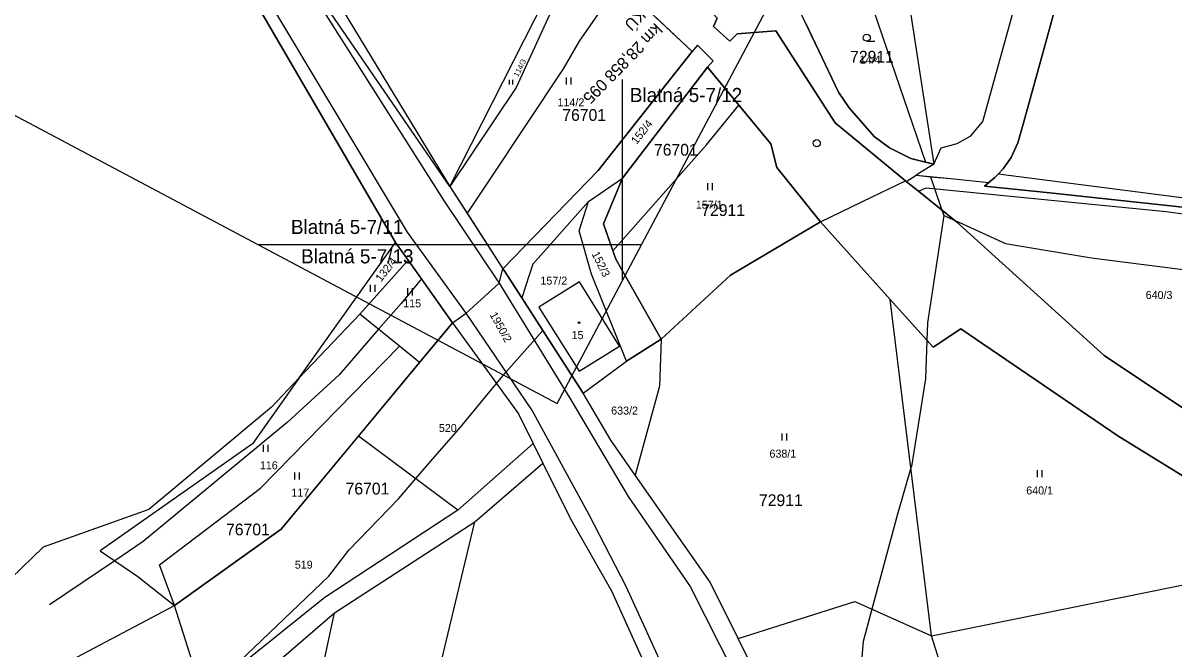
# Model space of a CAD drawing. Extents: x -794765 to -785424, y -1118958 to -1108731.
# Drawn here: x -789502.2 to -789257.8, y -1114585.8 to -1114452.9 of the extents above; entities that cross this region are included whole.
import ezdxf

# ---------------------------------------------------------------- set-up
doc = ezdxf.new("R2010")
doc.units = 0
for name, color, linetype in [('Level 66', 7, 'Continuous'), ('Level 71', 7, 'Continuous'), ('Level 75', 7, 'Continuous'), ('Level 76', 7, 'Continuous'), ('Level 77', 7, 'Continuous'), ('Level 78', 7, 'Continuous'), ('Level 79', 7, 'Continuous'), ('Level 81', 7, 'Continuous'), ('Vrstva 1', 7, 'Continuous'), ('Vrstva 53', 7, 'Continuous')]:
    doc.layers.add(name, color=color, linetype=linetype)

msp = doc.modelspace()

# ---------------------------------------------------------------- linework, layer by layer
at = {"layer": 'Level 66'}
for p, q in [((-789323.04, -1114456.77), (-789321.29, -1114456.77)), ((-789386.81, -1114465.98), (-789386.81, -1114464.48)), ((-789385.81, -1114465.98), (-789385.81, -1114464.48)), ((-789398.9, -1114465.95), (-789398.9, -1114464.95)), ((-789398.23, -1114465.95), (-789398.23, -1114464.95)), ((-789356.8, -1114488.4), (-789356.8, -1114486.9)), ((-789355.8, -1114488.4), (-789355.8, -1114486.9)), ((-789428.43, -1114510), (-789428.43, -1114508.5)), ((-789427.43, -1114510), (-789427.43, -1114508.5)), ((-789420.51, -1114510.74), (-789420.51, -1114509.24)), ((-789419.51, -1114510.74), (-789419.51, -1114509.24)), ((-789340.98, -1114541.58), (-789340.98, -1114540.08)), ((-789339.98, -1114541.58), (-789339.98, -1114540.08)), ((-789451.14, -1114543.99), (-789451.14, -1114542.49)), ((-789450.14, -1114543.99), (-789450.14, -1114542.49)), ((-789444.52, -1114549.86), (-789444.52, -1114548.36)), ((-789443.52, -1114549.86), (-789443.52, -1114548.36)), ((-789286.76, -1114549.37), (-789286.76, -1114547.87)), ((-789285.76, -1114549.37), (-789285.76, -1114547.87))]:
    msp.add_line(p, q, dxfattribs=at)
msp.add_circle((-789323.04, -1114456.02), 0.75, dxfattribs=at)
at = {"layer": 'Level 71'}
msp.add_lwpolyline([(-790360.41, -1114017.5), (-789388.79, -1114533.68), (-789259.98, -1114291.21)], dxfattribs=at)
at = {"layer": 'Level 75'}
for p, q in [((-789360.15, -1114458.92), (-789383.79, -1114436.65)), ((-789411.55, -1114487.64), (-789387.36, -1114439.86)), ((-789315.13, -1114441.52), (-789308.78, -1114482.88)), ((-789374.9, -1114485.84), (-789356.86, -1114462.31)), ((-789308.78, -1114482.88), (-789307.22, -1114479.43)), ((-789308.78, -1114482.88), (-789312.54, -1114485.23)), ((-789382.15, -1114490.8), (-789374.9, -1114485.84)), ((-789314.65, -1114486.55), (-789314.84, -1114486.39)), ((-789314.65, -1114486.55), (-789314.84, -1114486.39)), ((-789314.65, -1114486.55), (-789312.54, -1114485.23)), ((-789312.07, -1114488.61), (-789314.65, -1114486.55)), ((-789411.55, -1114487.64), (-789400.29, -1114505.09)), ((-789297.1, -1114486.75), (-789298.04, -1114487.53)), ((-789298.04, -1114487.53), (-789284.18, -1114488.99)), ((-789332.87, -1114495.13), (-789318.04, -1114511.65)), ((-789443.55, -1114528.27), (-789423.09, -1114499.54)), ((-789423.09, -1114499.54), (-789420.43, -1114503.28)), ((-789420.43, -1114503.28), (-789430.68, -1114514.72)), ((-789420.43, -1114503.28), (-789410.99, -1114516.56)), ((-789383.25, -1114531.51), (-789396.3, -1114511.28)), ((-789309.27, -1114583.03), (-789318.04, -1114511.65)), ((-789430.68, -1114514.72), (-789443.55, -1114528.27)), ((-789422.26, -1114521.55), (-789430.68, -1114514.72)), ((-789418, -1114525), (-789410.99, -1114516.56)), ((-789366.73, -1114520.04), (-789374.05, -1114524.74)), ((-789418, -1114525), (-789422.26, -1114521.55)), ((-789430.96, -1114540.62), (-789418, -1114525)), ((-789383.25, -1114531.51), (-789374.05, -1114524.74)), ((-789409.89, -1114556.32), (-789430.96, -1114540.62)), ((-789393.88, -1114542.19), (-789409.89, -1114556.32)), ((-789393.88, -1114542.19), (-789391.8, -1114546.4)), ((-789406.25, -1114558.84), (-789391.8, -1114546.4)), ((-789436.07, -1114578.19), (-789406.25, -1114558.84)), ((-789420.11, -1114616.54), (-789406.25, -1114558.84)), ((-789309.27, -1114583.03), (-789233.08, -1114567.59)), ((-789463.99, -1114595.65), (-789470.03, -1114576.58)), ((-789298.53, -1114616.71), (-789309.27, -1114583.03))]:
    msp.add_line(p, q, dxfattribs=at)
for points in [[(-789411.55, -1114487.64), (-789444.12, -1114440.1), (-789460.39, -1114416.23), (-789471.74, -1114406.17), (-789505.63, -1114376.09), (-789563.4, -1114324.15), (-789590.47, -1114299.37)], [(-789587.26, -1114300.1), (-789562.09, -1114321.4), (-789502.74, -1114374.33), (-789470.17, -1114403.72), (-789452.65, -1114419.15), (-789441.48, -1114438.37), (-789411.55, -1114487.64)], [(-789575.6, -1114332.86), (-789515.81, -1114384.07), (-789480.88, -1114415.35), (-789466.19, -1114428.84), (-789454.55, -1114445.52), (-789423.09, -1114499.54)], [(-789295.13, -1114484.99), (-789294.08, -1114483.87), (-789292.39, -1114481.46), (-789290.93, -1114478.35), (-789289.8, -1114474.35), (-789285.34, -1114458.22), (-789279.32, -1114436.33), (-789271.12, -1114410.79), (-789270.71, -1114410.22)], [(-789307.22, -1114479.43), (-789303.82, -1114478.46), (-789300.96, -1114476.84), (-789298.42, -1114473.84), (-789291.48, -1114448.78), (-789289.96, -1114449.38), (-789290.68, -1114440.44), (-789292.59, -1114437.73), (-789295.23, -1114435.63), (-789298.36, -1114434.17), (-789296.75, -1114428.57), (-789292.67, -1114429.19), (-789288.24, -1114427.96), (-789283.63, -1114424.14), (-789281.74, -1114420.18), (-789283.43, -1114419.82)], [(-789383.79, -1114436.65), (-789386.1, -1114441.7), (-789397.47, -1114466.61), (-789411.55, -1114487.64)], [(-789308.78, -1114482.88), (-789313.67, -1114481.68), (-789318.19, -1114479.4), (-789321.47, -1114476.97), (-789326.78, -1114470.92), (-789329.07, -1114467.56), (-789338.28, -1114448.1)], [(-789314.84, -1114486.39), (-789329.78, -1114474.08), (-789342.35, -1114454.54), (-789350.58, -1114455.19), (-789352.15, -1114456.75), (-789355.6, -1114453.64), (-789354.83, -1114451.89)], [(-789360.15, -1114458.92), (-789380.05, -1114484.2), (-789400.29, -1114505.09)], [(-789356.86, -1114462.31), (-789355.65, -1114460.93), (-789359, -1114457.59), (-789360.15, -1114458.92)], [(-789356.86, -1114462.31), (-789343.4, -1114478.53), (-789342.11, -1114483.58), (-789332.87, -1114495.13)], [(-789111.22, -1114470.02), (-789114.33, -1114476.68), (-789149.84, -1114486.32), (-789208.24, -1114494.14), (-789229.78, -1114493.4), (-789295.13, -1114484.99)], [(-789284.18, -1114488.99), (-789233.65, -1114494.43), (-789208.22, -1114495.86), (-789148.09, -1114487.9), (-789114.34, -1114478.64)], [(-789366.73, -1114520.04), (-789376.32, -1114503.06), (-789378.92, -1114495.53), (-789374.9, -1114485.84)], [(-789332.87, -1114495.13), (-789321.86, -1114489.79), (-789314.84, -1114486.39)], [(-789312.54, -1114485.23), (-789305.22, -1114485.95), (-789297.1, -1114486.75)], [(-789297.1, -1114486.75), (-789295.82, -1114485.71), (-789295.13, -1114484.99)], [(-789312.07, -1114488.61), (-789310.41, -1114487.87), (-789259.48, -1114492.92), (-789235.33, -1114496.28)], [(-789234.48, -1114549.02), (-789272.62, -1114523.48), (-789303.95, -1114495.11), (-789312.07, -1114488.61)], [(-789382.15, -1114490.8), (-789393.94, -1114504.09), (-789394.71, -1114506.43), (-789396.3, -1114511.28)], [(-789374.05, -1114524.74), (-789381.49, -1114506.27), (-789384.12, -1114497), (-789382.15, -1114490.8)], [(-789366.73, -1114520.04), (-789351.99, -1114506.47), (-789332.87, -1114495.13)], [(-789410.99, -1114516.56), (-789408.1, -1114514.5), (-789401.09, -1114508.13), (-789400.29, -1114505.09)], [(-789396.3, -1114511.28), (-789397.71, -1114509.09), (-789400.07, -1114505.43), (-789400.29, -1114505.09)], [(-789384.13, -1114526.83), (-789375.58, -1114521.52), (-789384.04, -1114507.86), (-789392.66, -1114513.22), (-789392.08, -1114514.15), (-789384.13, -1114526.83)], [(-789318.04, -1114511.65), (-789308.97, -1114521.75), (-789303.08, -1114517.85), (-789269.72, -1114540.6), (-789233.09, -1114563.18)], [(-789410.99, -1114516.56), (-789396.98, -1114535.89), (-789393.88, -1114542.19)], [(-789366.73, -1114520.04), (-789367.05, -1114530.02), (-789372.22, -1114548.94)], [(-789470.03, -1114576.58), (-789473.24, -1114567.94), (-789451.79, -1114551.65), (-789422.26, -1114521.55)], [(-789443.55, -1114528.27), (-789449.47, -1114534.51), (-789475.51, -1114556.18), (-789497.95, -1114564.23), (-789509.41, -1114575.22), (-789534.19, -1114601.87), (-789554.52, -1114590.86), (-789577.64, -1114602.12), (-789597.15, -1114613.07), (-789597.74, -1114600.43)], [(-789443.55, -1114528.27), (-789453.5, -1114542.25), (-789485.82, -1114565.02), (-789477.82, -1114570.42), (-789470.03, -1114576.58)], [(-789372.22, -1114548.94), (-789377.37, -1114541.51), (-789383.25, -1114531.51)], [(-789470.03, -1114576.58), (-789447.37, -1114560.39), (-789430.96, -1114540.62)], [(-789391.8, -1114546.4), (-789385.98, -1114558.19), (-789377.23, -1114573.5), (-789352.2, -1114628.9), (-789350.65, -1114631.28)], [(-789350.34, -1114583.64), (-789356.32, -1114571.64), (-789372.22, -1114548.94)], [(-789409.89, -1114556.32), (-789438.14, -1114574.88), (-789463.99, -1114595.65)], [(-789606.95, -1114640.95), (-789582.62, -1114635.01), (-789539.25, -1114613.22), (-789470.03, -1114576.58)], [(-789350.34, -1114583.64), (-789325.57, -1114575.75), (-789309.27, -1114583.03)], [(-789494.79, -1114613.58), (-789461.11, -1114599.74), (-789436.07, -1114578.19)], [(-789473.76, -1114714.5), (-789446.6, -1114627.26), (-789436.07, -1114578.19)], [(-789326.78, -1114632.68), (-789331.75, -1114620.93), (-789350.34, -1114583.64)]]:
    msp.add_lwpolyline(points, dxfattribs=at)
at = {"layer": 'Level 77'}
for p, q in [((-789445.06, -1114439.9), (-789412.76, -1114490.76)), ((-789420.6, -1114497.33), (-789452.44, -1114444.13)), ((-789412.76, -1114490.76), (-789401.09, -1114508.13)), ((-789408.1, -1114514.5), (-789420.6, -1114497.33)), ((-789401.09, -1114508.13), (-789386.13, -1114532.54)), ((-789394.2, -1114535.07), (-789408.1, -1114514.5)), ((-789386.13, -1114532.54), (-789373.7, -1114553.48)), ((-789382, -1114557.37), (-789394.2, -1114535.07)), ((-789373.7, -1114553.48), (-789360.57, -1114572.59)), ((-789374.1, -1114572.59), (-789382, -1114557.37)), ((-789348.92, -1114627.7), (-789374.1, -1114572.59)), ((-789360.57, -1114572.59), (-789335.44, -1114622.02))]:
    msp.add_line(p, q, dxfattribs=at)
at = {"layer": 'Level 78'}
for p, q in [((-789314.65, -1114486.55), (-789312.54, -1114485.23)), ((-789297.1, -1114486.75), (-789298.04, -1114487.53)), ((-789298.04, -1114487.53), (-789284.18, -1114488.99)), ((-789383.25, -1114531.51), (-789396.3, -1114511.28)), ((-789418, -1114525), (-789410.99, -1114516.56)), ((-789366.73, -1114520.04), (-789374.05, -1114524.74)), ((-789430.96, -1114540.62), (-789418, -1114525)), ((-789383.25, -1114531.51), (-789374.05, -1114524.74))]:
    msp.add_line(p, q, dxfattribs=at)
for points in [[(-789284.18, -1114488.99), (-789233.65, -1114494.43), (-789208.22, -1114495.86), (-789148.09, -1114487.9), (-789114.34, -1114478.64)], [(-789332.87, -1114495.13), (-789321.86, -1114489.79), (-789314.84, -1114486.39)], [(-789312.54, -1114485.23), (-789305.22, -1114485.95), (-789297.1, -1114486.75)], [(-789366.73, -1114520.04), (-789351.99, -1114506.47), (-789332.87, -1114495.13)], [(-789410.99, -1114516.56), (-789408.1, -1114514.5), (-789401.09, -1114508.13), (-789400.29, -1114505.09)], [(-789396.3, -1114511.28), (-789397.71, -1114509.09), (-789400.07, -1114505.43), (-789400.29, -1114505.09)], [(-789470.03, -1114576.58), (-789447.37, -1114560.39), (-789430.96, -1114540.62)], [(-789606.95, -1114640.95), (-789582.62, -1114635.01), (-789539.25, -1114613.22), (-789470.03, -1114576.58)]]:
    msp.add_lwpolyline(points, dxfattribs=at)
at = {"layer": 'Level 79'}
msp.add_circle((-789384.13, -1114516.53), 0.175, dxfattribs=at)
at = {"layer": 'Level 81'}
for p, q in [((-789323.72, -1114443.96), (-789310.56, -1114482.44)), ((-789357.07, -1114478.8), (-789350.2, -1114470.34)), ((-789376.93, -1114501.3), (-789357.07, -1114478.8)), ((-789400.29, -1114505.09), (-789380.05, -1114484.2)), ((-789407.91, -1114493.28), (-789400.29, -1114505.09)), ((-789332.87, -1114495.13), (-789351.99, -1114506.47)), ((-789410.99, -1114516.56), (-789417.6, -1114507.26)), ((-789351.99, -1114506.47), (-789366.73, -1114520.04))]:
    msp.add_line(p, q, dxfattribs=at)
for points in [[(-789400.13, -1114420.69), (-789449.47, -1114371.56), (-789470.68, -1114352.09), (-789500.91, -1114330.99), (-789534.18, -1114315.38), (-789561.38, -1114306.6), (-789587.26, -1114300.1), (-789562.09, -1114321.4), (-789502.74, -1114374.33), (-789470.17, -1114403.72), (-789452.65, -1114419.15), (-789441.48, -1114438.37), (-789411.55, -1114487.64), (-789407.91, -1114493.28)], [(-789210.57, -1114341.6), (-789223.34, -1114334.35), (-789252.39, -1114314.22), (-789250.9, -1114322.67), (-789251.18, -1114334.33), (-789253.33, -1114346.25), (-789257.56, -1114365.29), (-789262.46, -1114382.19), (-789263.02, -1114388.38), (-789264.73, -1114397.27), (-789267.29, -1114405.56), (-789270.71, -1114410.22), (-789271.12, -1114410.79), (-789279.32, -1114436.33), (-789285.34, -1114458.22), (-789289.8, -1114474.35), (-789290.93, -1114478.35), (-789292.39, -1114481.46), (-789294.08, -1114483.87), (-789295.13, -1114484.99), (-789295.82, -1114485.71), (-789297.1, -1114486.75)], [(-789417.6, -1114507.26), (-789420.43, -1114503.28), (-789423.09, -1114499.54), (-789454.55, -1114445.52), (-789466.19, -1114428.84), (-789480.88, -1114415.35), (-789515.81, -1114384.07), (-789575.6, -1114332.86), (-789576.73, -1114335.33), (-789599.87, -1114385.78), (-789603.26, -1114393.19), (-789604.86, -1114396.67)], [(-789375.58, -1114444.39), (-789384.14, -1114456.72), (-789387.54, -1114462.63), (-789403.26, -1114486.27), (-789407.91, -1114493.28)], [(-789380.05, -1114484.2), (-789360.15, -1114458.92), (-789375.58, -1114444.39)], [(-789310.56, -1114482.44), (-789308.78, -1114482.88), (-789307.22, -1114479.43), (-789303.82, -1114478.46), (-789300.96, -1114476.84), (-789298.42, -1114473.84), (-789291.48, -1114448.78)], [(-789336.02, -1114452.87), (-789329.07, -1114467.56), (-789326.78, -1114470.92), (-789321.47, -1114476.97), (-789318.19, -1114479.4), (-789313.67, -1114481.68), (-789310.56, -1114482.44)], [(-789309.5, -1114485.53), (-789305.22, -1114485.95), (-789297.1, -1114486.75), (-789298.04, -1114487.53), (-789284.18, -1114488.99), (-789233.65, -1114494.43), (-789208.22, -1114495.86), (-789148.09, -1114487.9), (-789114.34, -1114478.64), (-789108.83, -1114473.62), (-789102.63, -1114472.12), (-789086.93, -1114468.3), (-789058.11, -1114462.67), (-789015.34, -1114455.34), (-789012.6, -1114454.87), (-789012.14, -1114455.9), (-789009.91, -1114460.91)], [(-789350.2, -1114470.34), (-789356.86, -1114462.31), (-789374.9, -1114485.84), (-789378.92, -1114495.53), (-789376.93, -1114501.3)], [(-789306.68, -1114493.77), (-789304.24, -1114494.87), (-789293.55, -1114499.73), (-789275.34, -1114502.75), (-789238.07, -1114507.53), (-789235.44, -1114507.5), (-789200.79, -1114507.22), (-789182.14, -1114505.59), (-789165.19, -1114502.68), (-789156.72, -1114502.29), (-789146.12, -1114500.63), (-789139.76, -1114497.27), (-789108.83, -1114491.87), (-789104.67, -1114490.82), (-789097.67, -1114489.05), (-789075.77, -1114483.51), (-789058.39, -1114478.49), (-789036.35, -1114473.91), (-789021.31, -1114469.97), (-789015.99, -1114468.58), (-789009.22, -1114466.81)], [(-789332.87, -1114495.13), (-789342.11, -1114483.58), (-789343.4, -1114478.53), (-789350.2, -1114470.34)], [(-789108.83, -1114473.62), (-789114.34, -1114478.64), (-789148.09, -1114487.9), (-789208.22, -1114495.86), (-789233.65, -1114494.43), (-789284.18, -1114488.99), (-789298.04, -1114487.53), (-789297.1, -1114486.75)], [(-789391.84, -1114518.2), (-789383.25, -1114531.51), (-789374.05, -1114524.74), (-789366.73, -1114520.04), (-789351.99, -1114506.47), (-789332.87, -1114495.13), (-789321.86, -1114489.79), (-789314.84, -1114486.39), (-789314.65, -1114486.55), (-789312.54, -1114485.23), (-789309.5, -1114485.53)], [(-789309.5, -1114485.53), (-789308.64, -1114488.05), (-789307.08, -1114492.61), (-789306.68, -1114493.77)], [(-789306.68, -1114493.77), (-789310.11, -1114516.6), (-789310.25, -1114520.33), (-789310.55, -1114528.44), (-789313.55, -1114547.05), (-789313.65, -1114547.38), (-789316.53, -1114557.19), (-789321.94, -1114577.37), (-789323.78, -1114584.24), (-789324.64, -1114594.39), (-789325.51, -1114607.92), (-789322.16, -1114627.39), (-789319.72, -1114633.05), (-789316.67, -1114640.1), (-789314.56, -1114646.87), (-789310.76, -1114653.65), (-789301.47, -1114672.3), (-789300.2, -1114673.99), (-789289.64, -1114692.64), (-789280.29, -1114705.16)], [(-789376.93, -1114501.3), (-789376.32, -1114503.06), (-789366.73, -1114520.04)], [(-789470.03, -1114576.58), (-789447.37, -1114560.39), (-789430.96, -1114540.62), (-789418, -1114525), (-789410.99, -1114516.56), (-789408.1, -1114514.5), (-789401.09, -1114508.13), (-789400.29, -1114505.09), (-789400.07, -1114505.43), (-789397.71, -1114509.09), (-789396.3, -1114511.28), (-789391.84, -1114518.2)], [(-789417.6, -1114507.26), (-789421.94, -1114512.43), (-789426.71, -1114517.94), (-789435.1, -1114527.62), (-789446.13, -1114537.74), (-789476.68, -1114563.02)], [(-789410.99, -1114516.56), (-789418, -1114525), (-789447.37, -1114560.39), (-789470.03, -1114576.58)], [(-789463.85, -1114595.54), (-789461.06, -1114593.1), (-789437.29, -1114570.34), (-789433.05, -1114564.85), (-789422.44, -1114553.89), (-789418.82, -1114549.66), (-789415.22, -1114545.45), (-789409.28, -1114538.7), (-789401.64, -1114529.46), (-789399.51, -1114526.89), (-789391.84, -1114518.2)], [(-789476.68, -1114563.02), (-789482.73, -1114567.11), (-789496.62, -1114576.49)]]:
    msp.add_lwpolyline(points, dxfattribs=at)
at = {"layer": 'Vrstva 1'}
for p, q in [((-789375, -1114464.9), (-789375, -1114507.72)), ((-789370.9, -1114500), (-789452.2, -1114500))]:
    msp.add_line(p, q, dxfattribs=at)
msp.add_circle((-789333.65, -1114478.42), 0.75, dxfattribs=at)
at = {"layer": 'Vrstva 53'}
for points in [[(-789603.91, -1114286.39), (-789557.19, -1114296.51), (-789534.19, -1114304.37), (-789513.07, -1114313.2), (-789496.46, -1114322.71), (-789491.56, -1114325.89), (-789478.18, -1114334.57), (-789448.8, -1114359.16), (-789421.56, -1114385.77), (-789401.5, -1114405.4), (-789396.12, -1114409.35), (-789381.93, -1114424.44), (-789378.22, -1114428.46), (-789362.04, -1114444), (-789354.83, -1114451.89), (-789355.6, -1114453.64), (-789352.15, -1114456.75), (-789350.58, -1114455.19), (-789342.35, -1114454.54), (-789329.78, -1114474.08), (-789314.84, -1114486.39)], [(-789332.87, -1114495.13), (-789342.11, -1114483.58), (-789343.4, -1114478.53), (-789356.86, -1114462.31), (-789355.65, -1114460.93), (-789359, -1114457.59), (-789360.15, -1114458.92), (-789383.79, -1114436.65), (-789387.36, -1114439.86), (-789400.13, -1114420.69), (-789449.47, -1114371.56), (-789470.68, -1114352.09), (-789500.91, -1114330.99), (-789534.18, -1114315.38), (-789561.38, -1114306.6), (-789587.26, -1114300.1), (-789590.47, -1114299.37), (-789592.9, -1114298.82), (-789600.46, -1114294.39)], [(-789314.65, -1114486.55), (-789312.07, -1114488.61), (-789303.95, -1114495.11), (-789272.62, -1114523.48), (-789234.48, -1114549.02), (-789211.01, -1114563.21), (-789209.16, -1114564.33), (-789184.43, -1114575.03), (-789156.73, -1114587.01), (-789151.91, -1114588.58), (-789111.21, -1114601.86), (-789066.78, -1114612.81), (-789061.16, -1114614.19), (-789002.52, -1114626.82), (-788945.18, -1114640.28), (-788899.34, -1114649.59)], [(-789075.07, -1114623.43), (-789124.89, -1114611.37), (-789126.69, -1114610.58), (-789127.89, -1114610.16), (-789133.75, -1114612.63), (-789144.37, -1114617.13), (-789148.2, -1114602.99), (-789156.19, -1114600.12), (-789182.88, -1114588.76), (-789185.19, -1114587.78), (-789226.93, -1114566.34), (-789233.09, -1114563.18), (-789269.72, -1114540.6), (-789303.08, -1114517.85), (-789308.97, -1114521.75), (-789318.04, -1114511.65), (-789332.87, -1114495.13)]]:
    msp.add_lwpolyline(points, dxfattribs=at)

# ---------------------------------------------------------------- texts
at = {"layer": 'Level 76'}
for s, p in [('14/4', (-789324.53, -1114461.5)), ('114/2', (-789388.71, -1114470.59)), ('157/1', (-789359.34, -1114492.32)), ('157/2', (-789392.34, -1114508.46)), ('640/3', (-789263.81, -1114511.5)), ('115', (-789421.48, -1114513.28)), ('15', (-789385.73, -1114520.03)), ('633/2', (-789377.31, -1114536.05)), ('520', (-789413.91, -1114539.76)), ('638/1', (-789343.7, -1114545.2)), ('116', (-789451.92, -1114547.68)), ('117', (-789445.23, -1114553.47)), ('640/1', (-789289.17, -1114553.01)), ('519', (-789444.5, -1114568.78))]:
    msp.add_text(s, height=1.7, dxfattribs=at).set_placement(p)
for s, height, rotation, p in [('114/3', 1.14, 63, (-789397.1, -1114464.45)), ('152/4', 1.7, 52, (-789371.89, -1114478.79)), ('132/4', 1.7, 52, (-789426.18, -1114508)), ('152/3', 1.7, 296, (-789381.49, -1114501.92)), ('1950/2', 1.7, 299, (-789403.17, -1114514.85))]:
    msp.add_text(s, height=height, rotation=rotation, dxfattribs=at).set_placement(p)
at = {"layer": 'Level 81'}
for s, p in [('72911', (-789326.58, -1114461.31)), ('76701', (-789387.7, -1114473.68)), ('76701', (-789368.23, -1114481.07)), ('72911', (-789358.19, -1114493.89)), ('76701', (-789433.72, -1114553.02)), ('72911', (-789345.93, -1114555.49)), ('76701', (-789459.1, -1114561.7))]:
    msp.add_text(s, height=2.5, dxfattribs=at).set_placement(p)
at = {"layer": 'Vrstva 1'}
for s, p in [('KÚ', (-789371.48, -1114449.71)), ('km 28,858 095', (-789368.03, -1114452.77))]:
    msp.add_text(s, height=2.5, rotation=225.5203, dxfattribs=at).set_placement(p)
for s, p in [('Blatná 5-7/12', (-789373.35, -1114469.69)), ('Blatná 5-7/11', (-789445.32, -1114497.7)), ('Blatná 5-7/13', (-789443.16, -1114503.94))]:
    msp.add_text(s, height=3, dxfattribs=at).set_placement(p)

doc.saveas('drawing.dxf')
